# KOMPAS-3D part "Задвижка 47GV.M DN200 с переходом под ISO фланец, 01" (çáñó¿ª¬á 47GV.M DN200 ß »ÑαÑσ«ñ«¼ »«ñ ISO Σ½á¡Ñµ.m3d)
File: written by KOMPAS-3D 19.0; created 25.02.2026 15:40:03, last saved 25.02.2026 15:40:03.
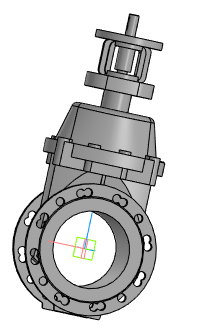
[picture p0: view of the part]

Document properties: Автор: Энергия; Полное имя файла: ..\..\47GVM\DR.47GVM.200.16.00.000\DR.47GVM.200.16.00.00 - Задвижка с обрезиненным клином DN200.a3d

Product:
- Part/product: Задвижка 47GV.M DN200 с переходом под ISO фланец  | designation 01
    Масса: 49.1505
  - Component [detail]: Корпус DN200  | pos. 3  | Материал: ВЧ50 ГОСТ 7293-85 (density 7200 kg/m3); Масса: 29.8323; Раздел спецификации: Детали; Форматы листов документа: 3xA3; source file: 47GV.M DN200\DR.47GVM.200.16.00.001 - Корпус.cdw, 47GV.M DN200\DR.47GVM.200.16.00.001 - Корпус.m3d
  - Component [detail]: Крышка DN200  | pos. 4  | Материал: ВЧ50 ГОСТ 7293-85 (density 7200 kg/m3); Масса: 8.49311; Раздел спецификации: Детали; Форматы листов документа: 2xA3; source file: 47GV.M DN200\DR.47GVM.200.16.00.002 - Крышка.cdw, 47GV.M DN200\DR.47GVM.200.16.00.002 - Крышка.m3d
  - Component [detail]: Шпиндель  | pos. 5  | Материал: Сталь 20Х13 ГОСТ 5632 - 2014 (density 7670 kg/m3); Масса: 1.57176; Раздел спецификации: Детали; Форматы листов документа: A3; source file: 47GV.M DN200\DR.47GVM.200.16.00.003 - Шпиндель.cdw, 47GV.M DN200\DR.47GVM.200.16.00.003 - Шпиндель.m3d
  - Component [assembly]: Клин с направляющими  | designation DR.47GVM.200.16.01.000  | pos. 2  | Масса: 7.86529; Раздел спецификации: Сборочные единицы; Форматы листов документа: A4; source file: 47GV.M DN200\DR.47GVM.200.16.01.000 - Клин с направляющими.a3d, 47GV.M DN200\DR.47GVM.200.16.01.000 - Клин с направляющими.spw, 47GV.M DN200\DR.47GVM.200.16.01.000 СБ - Клин с направляющими.cdw
  - Component [standard]: Кольцо A50.50 ХГА ГОСТ 13943-86  | pos. 48  | Материал: Сталь 50 ХГА ГОСТ 14959-2016 (density 1000 kg/m3); Масса: 0.0068; Раздел спецификации: Стандартные изделия; Рассекать на разрезах: no
  - Component: Стойка  | Материал: ВЧ50 ГОСТ 7293-85 (density 7200 kg/m3); Масса: 6.32319; Раздел спецификации: Детали; Форматы листов документа: 2xA3; source file: 47GV.M DN200\Стойка DN200.m3d
  - Component: Удлинитель шпинделя  | Материал: Сталь 20Х13 ГОСТ 5632-72 (density 7670 kg/m3); Масса: 1.03627; Раздел спецификации: Детали; Форматы листов документа: A3; source file: 47GV.M DN200\Удлинитель шпинделя DN200.m3d
- Part/product: Задвижка 47GV.M DN200 с переходом под ISO фланец
    Масса: 96.668
  - Component: Задвижка с обрезиненным клином DN200. Сборочный чертеж  | designation DR.47GVM.200.16.00.00СБ  | pos. 0  | Масса: 49.2062; Раздел спецификации: Документация; Форматы листов документа: 2xA3; source file: 47GV.M DN200\DR.47GVM.200.16.00.000 СБ - Задвижка с обрезиненным клином DN200.cdw

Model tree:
1. Операция без истории:1

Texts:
  Точка начала. Х
  Точка начала. Y
  Точка начала. Z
